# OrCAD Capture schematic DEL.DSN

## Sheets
1 PAGE2
2 PAGE1: size A4
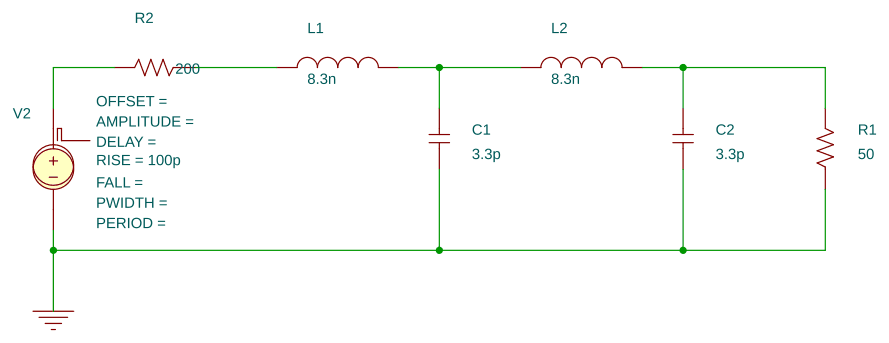
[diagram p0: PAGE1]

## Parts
C1  3.3p  [CK05]
C2  3.3p  [CK05]
L1  8.3n  [L2012C]
L2  8.3n  [L2012C]
R1  50  [RC05]
R2  200  [RC05]
V2  ?DC|DC @DC| ?AC|AC @AC|\n+PULSE @OFFSET @AMPLITUDE+@OFFSET ?DELAY/@DELAY/~DELAY/0/ #RISE/@RISE/ #FALL/@FALL/ #PWIDTH/@PWIDTH/ #PERIOD/@PERIOD/

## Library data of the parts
C1 C2 = C
L1 L2 = L
R1 R2 = R
V2 = V_PULSE: RISE: 100p

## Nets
0: C1.1 C2.1 R1.1 V2.1(NVS)
N01755: C1.2 L1.2 L2.1
N02491: C2.2 L2.2 R1.2
N11257: R2.2 V2.2(PVS)
N11273: L1.1 R2.1
